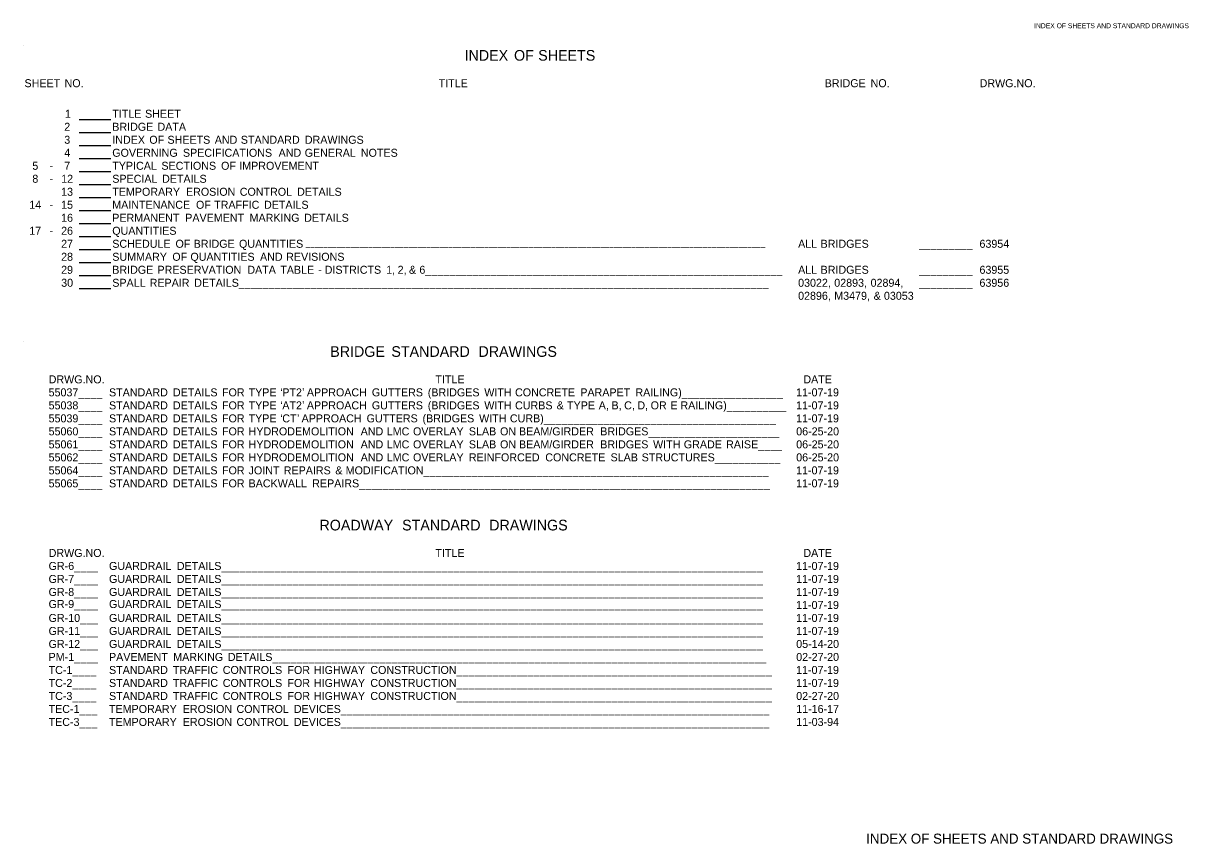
# Model space of a CAD drawing. Extents: x 1930556 to 1931949, y 596452 to 599544.
import ezdxf

# ---------------------------------------------------------------- set-up
doc = ezdxf.new("R2010")
doc.units = 0
for name, color, linetype in [('Default', 7, 'Continuous'), ('R_Border', 7, 'Continuous'), ('R_Border Prem', 7, 'Continuous')]:
    doc.layers.add(name, color=color, linetype=linetype)

msp = doc.modelspace()

# ---------------------------------------------------------------- linework, layer by layer
at = {"layer": 'Default'}
for p, q in [((1930556.1, 599518), (1930556.1, 599518)), ((1930623.2, 599429.1), (1930661.4, 599429.1)), ((1930623.2, 599413.5), (1930661.4, 599413.5)), ((1930623.2, 599397.9), (1930661.4, 599397.9)), ((1930623.2, 599382.3), (1930661.4, 599382.3)), ((1930623.2, 599366.7), (1930661.4, 599366.7)), ((1930623.2, 599351.1), (1930661.4, 599351.1)), ((1930623.2, 599335.5), (1930661.4, 599335.5)), ((1930623.2, 599319.9), (1930661.4, 599319.9)), ((1930623.2, 599304.3), (1930661.4, 599304.3)), ((1930623.2, 599288.7), (1930661.4, 599288.7)), ((1930623.2, 599273.1), (1930661.4, 599273.1)), ((1930623.2, 599257.5), (1930661.4, 599257.5)), ((1930623.2, 599241.9), (1930661.4, 599241.9)), ((1930623.2, 599226.3), (1930661.4, 599226.3)), ((1930556.1, 599162.6), (1930556.1, 599162.6))]:
    msp.add_line(p, q, dxfattribs=at)

# ---------------------------------------------------------------- texts
for s, height, p in [('INDEX', 12.8, (1931085.7, 599499.5)), (' OF', 12.8, (1931140.3, 599499.5)), (' SHEETS', 12.8, (1931169.3, 599499.5)), ('SHEET', 9.6, (1930557.7, 599467.7)), (' NO.', 9.6, (1930602.2, 599467.7)), ('TITLE', 9.6, (1931054.6, 599467.7)), ('BRIDGE', 9.6, (1931517.8, 599467.7)), (' NO.', 9.6, (1931569.3, 599467.7)), ('DRWG.NO.', 9.6, (1931703.7, 599467.7)), ('1', 9.6, (1930606.3, 599431)), ('TITLE', 9.6, (1930663, 599431)), (' SHEET', 9.6, (1930698.8, 599431)), ('2', 9.6, (1930605.4, 599415.4)), ('BRIDGE', 9.6, (1930663, 599415.4)), (' DATA', 9.6, (1930713.7, 599415.4)), ('3', 9.6, (1930605.4, 599399.8)), ('INDEX', 9.6, (1930663, 599399.8)), (' OF', 9.6, (1930703.9, 599399.8)), (' SHEETS', 9.6, (1930725.7, 599399.8)), (' AND', 9.6, (1930782.4, 599399.8)), (' STANDARD', 9.6, (1930813.7, 599399.8)), (' DRAWINGS', 9.6, (1930890.5, 599399.8)), ('4', 9.6, (1930605.4, 599384.2)), ('GOVERNING', 9.6, (1930663, 599384.2)), (' SPECIFICATIONS', 9.6, (1930744.2, 599384.2)), (' AND', 9.6, (1930859, 599384.2)), (' GENERAL', 9.6, (1930890.3, 599384.2)), (' NOTES', 9.6, (1930957.7, 599384.2)), ('5', 9.6, (1930567.1, 599368.6)), ('7', 9.6, (1930605.4, 599368.6)), ('TYPICAL', 9.6, (1930663, 599368.6)), (' SECTIONS', 9.6, (1930718.4, 599368.6)), (' OF', 9.6, (1930790, 599368.6)), (' IMPROVEMENT', 9.6, (1930811.8, 599368.6)), ('8', 9.6, (1930567.1, 599353)), ('-', 9.6, (1930587.7, 599368.6)), ('12', 9.6, (1930601.7, 599353)), ('SPECIAL', 9.6, (1930663, 599353)), (' DETAILS', 9.6, (1930719.2, 599353)), ('-', 9.6, (1930587.7, 599353)), ('13', 9.6, (1930601.6, 599337.4)), ('TEMPORARY', 9.6, (1930663, 599337.4)), (' EROSION', 9.6, (1930747.9, 599337.4)), (' CONTROL', 9.6, (1930812.4, 599337.4)), (' DETAILS', 9.6, (1930881.2, 599337.4)), ('14', 9.6, (1930563.4, 599321.8)), ('-', 9.6, (1930587.7, 599321.8)), ('15', 9.6, (1930601.6, 599321.8)), ('MAINTENANCE', 9.6, (1930663, 599321.8)), (' OF', 9.6, (1930759.9, 599321.8)), (' TRAFFIC', 9.6, (1930781.7, 599321.8)), (' DETAILS', 9.6, (1930841.5, 599321.8)), ('16', 9.6, (1930601.6, 599306.2)), ('PERMANENT', 9.6, (1930663, 599306.2)), (' PAVEMENT', 9.6, (1930747, 599306.2)), (' MARKING', 9.6, (1930824.2, 599306.2)), (' DETAILS', 9.6, (1930889.7, 599306.2)), ('17', 9.6, (1930563.4, 599290.6)), ('-', 9.6, (1930587.7, 599290.6)), ('26', 9.6, (1930601.6, 599290.6)), ('QUANTITIES', 9.6, (1930663, 599290.6)), ('27', 9.6, (1930601.6, 599275)), ('SCHEDULE', 9.6, (1930663, 599275)), (' OF', 9.6, (1930735.3, 599275)), (' BRIDGE', 9.6, (1930757.1, 599275)), (' QUANTITIES', 9.6, (1930811.5, 599275)), ('ALL', 9.6, (1931485.9, 599275)), (' BRIDGES', 9.6, (1931509.3, 599275)), ('63954', 9.6, (1931703.5, 599275)), ('28', 9.6, (1930601.6, 599259.4)), ('SUMMARY', 9.6, (1930663, 599259.4)), (' OF', 9.6, (1930731.5, 599259.4)), (' QUANTITIES', 9.6, (1930753.2, 599259.4)), (' AND', 9.6, (1930836.7, 599259.4)), (' REVISIONS', 9.6, (1930868.1, 599259.4)), ('_______________________________________________________________________________________________________', 7.2, (1930895, 599277.4)), ('_________', 9.6, (1931631, 599275)), ('29', 9.6, (1930601.6, 599243.8)), ('BRIDGE', 9.6, (1930663, 599243.8)), (' PRESERVATION', 9.6, (1930713.7, 599243.8)), (' DATA', 9.6, (1930821.5, 599243.8)), (' TABLE', 9.6, (1930861, 599243.8)), (' DISTRICTS', 9.6, (1930914.3, 599243.8)), (' 1,', 9.6, (1930988.1, 599243.8)), (' 2,', 9.6, (1931001.8, 599243.8)), (' &', 9.6, (1931015.5, 599243.8)), (' 6____________________________________________________________', 9.6, (1931027.9, 599243.8)), ('ALL', 9.6, (1931485.9, 599243.8)), (' BRIDGES', 9.6, (1931509.3, 599243.8)), ('63955', 9.6, (1931703.5, 599243.8)), ('30', 9.6, (1930601.7, 599228.2)), ('SPALL', 9.6, (1930663, 599228.2)), (' REPAIR', 9.6, (1930704.3, 599228.2)), (' DETAILS_________________________________________________________________________________________', 9.6, (1930757.8, 599228.2)), (' -', 9.6, (1930906.5, 599243.8)), ('03022,', 9.6, (1931485.9, 599228.2)), (' 02893,', 9.6, (1931525.7, 599228.2)), (' 02894,', 9.6, (1931569.3, 599228.2)), ('_________', 9.6, (1931631, 599243.8)), ('63956', 9.6, (1931703.5, 599228.2)), ('02896,', 9.6, (1931485.9, 599212.6)), (' M3479,', 9.6, (1931525.7, 599212.6)), (' &', 9.6, (1931573, 599212.6)), (' 03053', 9.6, (1931585.3, 599212.6)), ('_________', 9.6, (1931631, 599228.2)), ('BRIDGE', 12.8, (1930924.5, 599144.1)), (' STANDARD', 12.8, (1930993.1, 599144.1)), (' DRAWINGS', 12.8, (1931097.6, 599144.1)), ('DRWG.NO.', 9.6, (1930586.7, 599112.3)), ('TITLE', 9.6, (1931050.7, 599112.3)), ('DATE', 9.6, (1931492.2, 599112.3)), ('55037____', 9.6, (1930586.6, 599096.7)), ('STANDARD', 9.6, (1930659.1, 599096.7)), (' DETAILS', 9.6, (1930732.2, 599096.7)), (' FOR', 9.6, (1930791.1, 599096.7)), (' TYPE', 9.6, (1930823, 599096.7)), ('‘', 9.6, (1930864.7, 599096.7)), ('PT2', 9.6, (1930867, 599096.7)), ('’', 9.6, (1930890.8, 599096.7)), (' APPROACH', 9.6, (1930892.9, 599096.7)), (' GUTTERS', 9.6, (1930970.9, 599096.7)), (' (BRIDGES', 9.6, (1931038, 599096.7)), (' WITH', 9.6, (1931105.8, 599096.7)), (' CONCRETE', 9.6, (1931142.7, 599096.7)), (' PARAPET', 9.6, (1931221, 599096.7)), (' RAILING)_________________', 9.6, (1931287.1, 599096.7)), ('11-07-19', 9.6, (1931483.5, 599096.7)), ('55038____', 9.6, (1930586.6, 599081.1)), ('STANDARD', 9.6, (1930659.1, 599081.1)), (' DETAILS', 9.6, (1930732.2, 599081.1)), (' FOR', 9.6, (1930791.1, 599081.1)), (' TYPE', 9.6, (1930823, 599081.1)), ('‘', 9.6, (1930864.7, 599081.1)), ('AT2', 9.6, (1930867, 599081.1)), ('’', 9.6, (1930890.8, 599081.1)), (' APPROACH', 9.6, (1930892.9, 599081.1)), (' GUTTERS', 9.6, (1930970.9, 599081.1)), (' (BRIDGES', 9.6, (1931038, 599081.1)), (' WITH', 9.6, (1931105.8, 599081.1)), (' CURBS', 9.6, (1931142.7, 599081.1)), (' &', 9.6, (1931192.7, 599081.1)), (' TYPE', 9.6, (1931205.1, 599081.1)), (' A,', 9.6, (1931243.1, 599081.1)), (' B,', 9.6, (1931258.4, 599081.1)), (' C,', 9.6, (1931273.6, 599081.1)), (' D,', 9.6, (1931289.5, 599081.1)), (' OR', 9.6, (1931305.4, 599081.1)), (' E', 9.6, (1931329.1, 599081.1)), (' RAILING)__________', 9.6, (1931341.1, 599081.1)), ('11-07-19', 9.6, (1931483.5, 599081.1)), ('55039____', 9.6, (1930586.6, 599065.5)), ('STANDARD', 9.6, (1930659.1, 599065.5)), (' DETAILS', 9.6, (1930732.2, 599065.5)), (' FOR', 9.6, (1930791.1, 599065.5)), (' TYPE', 9.6, (1930823, 599065.5)), ('‘', 9.6, (1930864.7, 599065.5)), ('CT', 9.6, (1930867, 599065.5)), ('’', 9.6, (1930884.6, 599065.5)), (' APPROACH', 9.6, (1930886.6, 599065.5)), (' GUTTERS', 9.6, (1930964.6, 599065.5)), (' (BRIDGES', 9.6, (1931031.7, 599065.5)), (' WITH', 9.6, (1931099.6, 599065.5)), (' CURB)_______________________________________', 9.6, (1931136.5, 599065.5)), ('11-07-19', 9.6, (1931483.5, 599065.5)), ('55060____', 9.6, (1930586.6, 599049.9)), ('STANDARD', 9.6, (1930659.1, 599049.9)), (' DETAILS', 9.6, (1930732.2, 599049.9)), (' FOR', 9.6, (1930791.1, 599049.9)), (' HYDRODEMOLITION', 9.6, (1930823, 599049.9)), (' AND', 9.6, (1930957.5, 599049.9)), (' LMC', 9.6, (1930988.8, 599049.9)), (' OVERLAY', 9.6, (1931020.3, 599049.9)), (' SLAB', 9.6, (1931087.3, 599049.9)), (' ON', 9.6, (1931124.7, 599049.9)), (' BEAM/GIRDER', 9.6, (1931147.4, 599049.9)), (' BRIDGES______________________', 9.6, (1931244.9, 599049.9)), ('06-25-20', 9.6, (1931483.6, 599049.9)), ('55061____', 9.6, (1930586.6, 599034.3)), ('STANDARD', 9.6, (1930659.1, 599034.3)), (' DETAILS', 9.6, (1930732.2, 599034.3)), (' FOR', 9.6, (1930791.1, 599034.3)), (' HYDRODEMOLITION', 9.6, (1930823, 599034.3)), (' AND', 9.6, (1930957.5, 599034.3)), (' LMC', 9.6, (1930988.8, 599034.3)), (' OVERLAY', 9.6, (1931020.3, 599034.3)), (' SLAB', 9.6, (1931087.3, 599034.3)), (' ON', 9.6, (1931124.7, 599034.3)), (' BEAM/GIRDER', 9.6, (1931147.4, 599034.3)), (' BRIDGES', 9.6, (1931244.9, 599034.3)), (' WITH', 9.6, (1931308.3, 599034.3)), (' GRADE', 9.6, (1931345.2, 599034.3)), (' RAISE____', 9.6, (1931395.9, 599034.3)), ('06-25-20', 9.6, (1931483.6, 599034.3)), ('55062____', 9.6, (1930586.6, 599018.7)), ('STANDARD', 9.6, (1930659.1, 599018.7)), (' DETAILS', 9.6, (1930732.2, 599018.7)), (' FOR', 9.6, (1930791.1, 599018.7)), (' HYDRODEMOLITION', 9.6, (1930823, 599018.7)), (' AND', 9.6, (1930957.5, 599018.7)), (' LMC', 9.6, (1930988.8, 599018.7)), (' OVERLAY', 9.6, (1931020.3, 599018.7)), (' REINFORCED', 9.6, (1931087.3, 599018.7)), (' CONCRETE', 9.6, (1931179, 599018.7)), (' SLAB', 9.6, (1931257.3, 599018.7)), (' STRUCTURES___________', 9.6, (1931294.6, 599018.7)), ('06-25-20', 9.6, (1931483.6, 599018.7)), ('55064____', 9.6, (1930586.6, 599003.1)), ('STANDARD', 9.6, (1930659.1, 599003.1)), (' DETAILS', 9.6, (1930732.2, 599003.1)), (' FOR', 9.6, (1930791.1, 599003.1)), (' JOINT', 9.6, (1930823, 599003.1)), (' REPAIRS', 9.6, (1930865.2, 599003.1)), (' &', 9.6, (1930927.1, 599003.1)), (' MODIFICATION__________________________________________________________', 9.6, (1930939.5, 599003.1)), ('11-07-19', 9.6, (1931483.5, 599003.1)), ('55065____', 9.6, (1930586.6, 598987.5)), ('STANDARD', 9.6, (1930659.1, 598987.5)), (' DETAILS', 9.6, (1930732.2, 598987.5)), (' FOR', 9.6, (1930791.1, 598987.5)), (' BACKWALL', 9.6, (1930823, 598987.5)), (' REPAIRS_____________________________________________________________________', 9.6, (1930899.3, 598987.5)), ('11-07-19', 9.6, (1931483.5, 598987.5)), ('ROADWAY', 12.8, (1930911.6, 598935.8)), (' STANDARD', 12.8, (1931006, 598935.8)), (' DRAWINGS', 12.8, (1931110.5, 598935.8)), ('DRWG.NO.', 9.6, (1930586.7, 598904)), ('TITLE', 9.6, (1931050.7, 598904)), ('DATE', 9.6, (1931492.2, 598904)), ('GR-6____', 9.6, (1930586.6, 598888.4)), ('GUARDRAIL', 9.6, (1930659.1, 598888.4)), (' DETAILS___________________________________________________________________________________________', 9.6, (1930736.9, 598888.4)), ('11-07-19', 9.6, (1931483.5, 598888.4)), ('GR-7____', 9.6, (1930586.6, 598872.8)), ('GUARDRAIL', 9.6, (1930659.1, 598872.8)), (' DETAILS___________________________________________________________________________________________', 9.6, (1930736.9, 598872.8)), ('11-07-19', 9.6, (1931483.5, 598872.8)), ('GR-8____', 9.6, (1930586.6, 598857.2)), ('GUARDRAIL', 9.6, (1930659.1, 598857.2)), (' DETAILS___________________________________________________________________________________________', 9.6, (1930736.9, 598857.2)), ('11-07-19', 9.6, (1931483.5, 598857.2)), ('GR-9____', 9.6, (1930586.6, 598842.7)), ('GUARDRAIL', 9.6, (1930659.1, 598842.7)), (' DETAILS___________________________________________________________________________________________', 9.6, (1930736.9, 598842.7)), ('11-07-19', 9.6, (1931483.5, 598841.6)), ('GR-10___', 9.6, (1930586.6, 598826)), ('GUARDRAIL', 9.6, (1930659.1, 598826)), (' DETAILS___________________________________________________________________________________________', 9.6, (1930736.9, 598826)), ('11-07-19', 9.6, (1931483.5, 598826)), ('GR-11___', 9.6, (1930586.6, 598810.4)), ('GUARDRAIL', 9.6, (1930659.1, 598810.4)), (' DETAILS___________________________________________________________________________________________', 9.6, (1930736.9, 598810.4)), ('11-07-19', 9.6, (1931483.5, 598810.4)), ('GR-12___', 9.6, (1930586.6, 598794.8)), ('GUARDRAIL', 9.6, (1930659.1, 598794.8)), (' DETAILS___________________________________________________________________________________________', 9.6, (1930736.9, 598794.8)), ('05-14-20', 9.6, (1931483.6, 598794.8)), ('PM-1____', 9.6, (1930586.6, 598779.2)), ('PAVEMENT', 9.6, (1930659.1, 598779.2)), (' MARKING', 9.6, (1930732.6, 598779.2)), (' DETAILS___________________________________________________________________________________', 9.6, (1930798.1, 598779.2)), ('02-27-20', 9.6, (1931483.6, 598779.2)), ('TC-1____', 9.6, (1930586.6, 598763.6)), ('STANDARD', 9.6, (1930659.1, 598763.6)), (' TRAFFIC', 9.6, (1930732.2, 598763.6)), (' CONTROLS', 9.6, (1930792, 598763.6)), (' FOR', 9.6, (1930869.6, 598763.6)), (' HIGHWAY', 9.6, (1930901.4, 598763.6)), (' CONSTRUCTION_____________________________________________________', 9.6, (1930969.1, 598763.6)), ('11-07-19', 9.6, (1931483.5, 598763.6)), ('TC-2____', 9.6, (1930586.6, 598748)), ('STANDARD', 9.6, (1930659.1, 598748)), (' TRAFFIC', 9.6, (1930732.2, 598748)), (' CONTROLS', 9.6, (1930792, 598748)), (' FOR', 9.6, (1930869.6, 598748)), (' HIGHWAY', 9.6, (1930901.4, 598748)), (' CONSTRUCTION_____________________________________________________', 9.6, (1930969.1, 598748)), ('11-07-19', 9.6, (1931483.5, 598748)), ('TC-3____', 9.6, (1930586.6, 598732.4)), ('STANDARD', 9.6, (1930659.1, 598732.4)), (' TRAFFIC', 9.6, (1930732.2, 598732.4)), (' CONTROLS', 9.6, (1930792, 598732.4)), (' FOR', 9.6, (1930869.6, 598732.4)), (' HIGHWAY', 9.6, (1930901.4, 598732.4)), (' CONSTRUCTION_____________________________________________________', 9.6, (1930969.1, 598732.4)), ('02-27-20', 9.6, (1931483.6, 598732.4)), ('TEC-1___', 9.6, (1930586.6, 598716.8)), ('TEMPORARY', 9.6, (1930659.1, 598716.8)), (' EROSION', 9.6, (1930744, 598716.8)), (' CONTROL', 9.6, (1930808.5, 598716.8)), (' DEVICES________________________________________________________________________', 9.6, (1930877.3, 598716.8)), ('11-16-17', 9.6, (1931483.6, 598716.8)), ('TEC-3___', 9.6, (1930586.6, 598701.2)), ('TEMPORARY', 9.6, (1930659.1, 598701.2)), (' EROSION', 9.6, (1930744, 598701.2)), (' CONTROL', 9.6, (1930808.5, 598701.2)), (' DEVICES________________________________________________________________________', 9.6, (1930877.3, 598701.2)), ('11-03-94', 9.6, (1931483.6, 598701.2))]:
    msp.add_text(s, height=height, rotation=360, dxfattribs=at).set_placement(p)
at = {"layer": 'R_Border'}
msp.add_text('INDEX OF SHEETS AND STANDARD DRAWINGS', height=12, rotation=360, dxfattribs=at).set_placement((1931567.6, 598560))
at = {"layer": 'R_Border Prem'}
msp.add_text('INDEX OF SHEETS AND STANDARD DRAWINGS', height=5.862, rotation=360, dxfattribs=at).set_placement((1931769.1, 599538.5))

doc.saveas('drawing.dxf')
